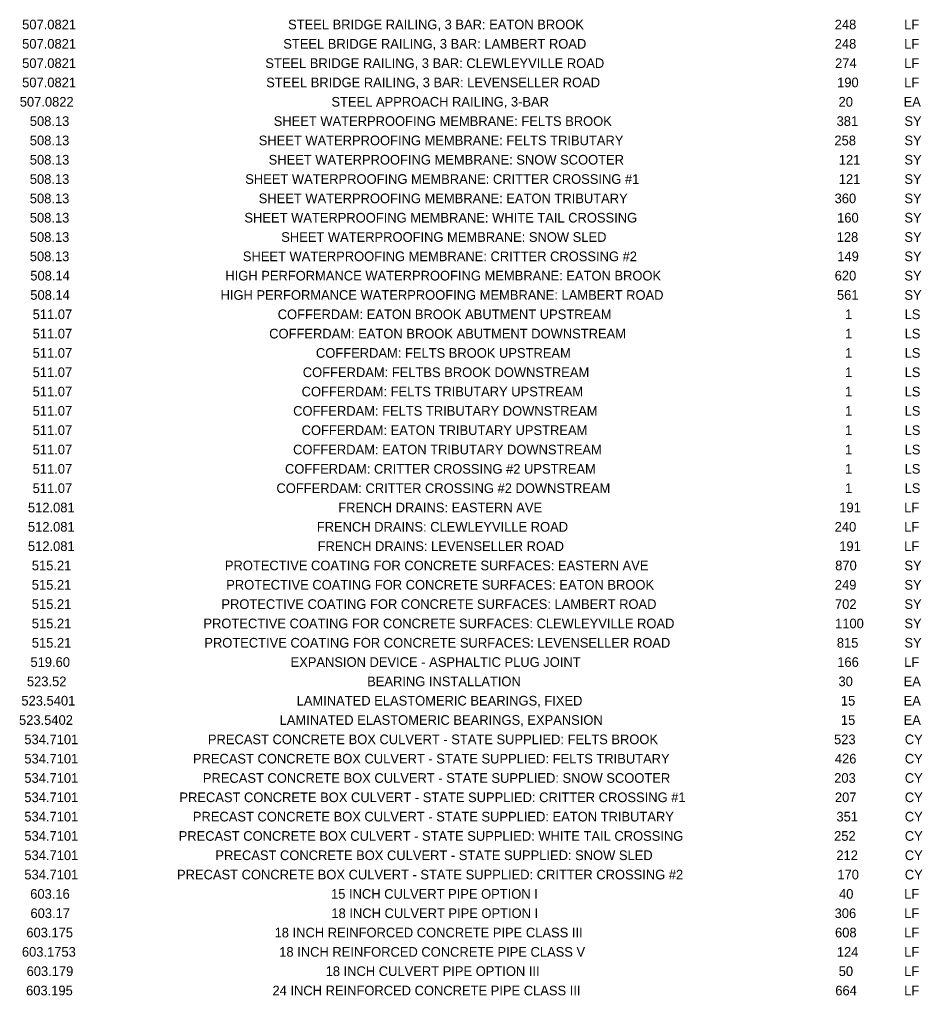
# Model space of a CAD drawing. Extents: x -18.7 to 5.6, y -2.7 to 5.1.
# Drawn here: x -18.677 to -17.757, y 1.164 to 2.159 of the extents above; entities that cross this region are included whole.
import ezdxf

# ---------------------------------------------------------------- set-up
doc = ezdxf.new("R2010")
doc.units = 0
doc.layers.add('ANNOTATION', color=7, linetype='Continuous')

msp = doc.modelspace()

# ---------------------------------------------------------------- texts
at = {"layer": 'ANNOTATION'}
for s, height, p in [('507.0821', 0.009843, (-18.674, 2.14859)), ('STEEL BRIDGE RAILING, 3 BAR: EATON BROOK', 0.009843, (-18.40311, 2.14859)), ('248', 0.009843, (-17.84626, 2.14859)), ('LF', 0.009843, (-17.77549, 2.14859)), ('507.0821', 0.009843, (-18.674, 2.1289)), ('STEEL BRIDGE RAILING, 3 BAR: LAMBERT ROAD', 0.009843, (-18.408, 2.1289)), ('248', 0.009843, (-17.84626, 2.1289)), ('LF', 0.009843, (-17.77549, 2.1289)), ('507.0821', 0.009843, (-18.674, 2.10921)), ('STEEL BRIDGE RAILING, 3 BAR: CLEWLEYVILLE ROAD', 0.009843, (-18.42633, 2.10921)), ('274', 0.009843, (-17.84592, 2.10921)), ('LF', 0.009843, (-17.77549, 2.10921)), ('507.0821', 0.009843, (-18.674, 2.08953)), ('STEEL BRIDGE RAILING, 3 BAR: LEVENSELLER ROAD', 0.009843, (-18.42543, 2.08953)), ('190', 0.009843, (-17.84382, 2.08953)), ('LF', 0.009843, (-17.77549, 2.08953)), ('507.0822', 0.009843, (-18.67644, 2.06984)), ('STEEL APPROACH RAILING, 3-BAR', 0.009843, (-18.35896, 2.06984)), ('20', 0.009843, (-17.84235, 2.06984)), ('EA', 0.009843, (-17.77611, 2.06984)), ('508.13', 0.009843, (-18.66621, 2.05016)), ('SHEET WATERPROOFING MEMBRANE: FELTS BROOK', 0.009843, (-18.41775, 2.05016)), ('381', 0.009843, (-17.84436, 2.05016)), ('SY', 0.009843, (-17.77526, 2.05016)), ('508.13', 0.009843, (-18.66621, 2.03047)), ('SHEET WATERPROOFING MEMBRANE: FELTS TRIBUTARY', 0.009843, (-18.43302, 2.03047)), ('258', 0.009843, (-17.84657, 2.03047)), ('SY', 0.009843, (-17.77526, 2.03047)), ('508.13', 0.009843, (-18.66621, 2.01078)), ('SHEET WATERPROOFING MEMBRANE: SNOW SCOOTER', 0.009843, (-18.4229, 2.01078)), ('121', 0.009843, (-17.84212, 2.01078)), ('SY', 0.009843, (-17.77526, 2.01078)), ('508.13', 0.009843, (-18.66621, 1.9911)), ('SHEET WATERPROOFING MEMBRANE: CRITTER CROSSING #1', 0.009843, (-18.44676, 1.9911)), ('121', 0.009843, (-17.84212, 1.9911)), ('SY', 0.009843, (-17.77526, 1.9911)), ('508.13', 0.009843, (-18.66621, 1.97141)), ('SHEET WATERPROOFING MEMBRANE: EATON TRIBUTARY', 0.009843, (-18.43306, 1.97141)), ('360', 0.009843, (-17.84638, 1.97141)), ('SY', 0.009843, (-17.77526, 1.97141)), ('508.13', 0.009843, (-18.66621, 1.95173)), ('SHEET WATERPROOFING MEMBRANE: WHITE TAIL CROSSING', 0.009843, (-18.44756, 1.95173)), ('160', 0.009843, (-17.84382, 1.95173)), ('SY', 0.009843, (-17.77526, 1.95173)), ('508.13', 0.009843, (-18.66621, 1.93204)), ('SHEET WATERPROOFING MEMBRANE: SNOW SLED', 0.009843, (-18.41009, 1.93204)), ('128', 0.009843, (-17.84425, 1.93204)), ('SY', 0.009843, (-17.77526, 1.93204)), ('508.13', 0.009843, (-18.66621, 1.91235)), ('SHEET WATERPROOFING MEMBRANE: CRITTER CROSSING #2', 0.009843, (-18.4492, 1.91235)), ('149', 0.009843, (-17.84367, 1.91235)), ('SY', 0.009843, (-17.77526, 1.91235)), ('508.14', 0.009843, (-18.6657, 1.89267)), ('HIGH PERFORMANCE WATERPROOFING MEMBRANE: EATON BROOK', 0.009843, (-18.467, 1.89267)), ('620', 0.009843, (-17.8463, 1.89267)), ('SY', 0.009843, (-17.77526, 1.89267)), ('508.14', 0.009843, (-18.6657, 1.87298)), ('HIGH PERFORMANCE WATERPROOFING MEMBRANE: LAMBERT ROAD', 0.009843, (-18.47189, 1.87298)), ('561', 0.009843, (-17.84398, 1.87298)), ('SY', 0.009843, (-17.77526, 1.87298)), ('511.07', 0.009843, (-18.6633, 1.8533)), ('COFFERDAM: EATON BROOK ABUTMENT UPSTREAM', 0.009843, (-18.41366, 1.8533)), ('1', 0.00984, (-17.83576, 1.8533)), ('LS', 0.009843, (-17.77506, 1.8533)), ('511.07', 0.009843, (-18.6633, 1.83361)), ('COFFERDAM: EATON BROOK ABUTMENT DOWNSTREAM', 0.009843, (-18.42234, 1.83361)), ('1', 0.00984, (-17.83576, 1.83361)), ('LS', 0.009843, (-17.77506, 1.83361)), ('511.07', 0.009843, (-18.6633, 1.81392)), ('COFFERDAM: FELTS BROOK UPSTREAM', 0.009843, (-18.37471, 1.81392)), ('1', 0.00984, (-17.83576, 1.81392)), ('LS', 0.009843, (-17.77506, 1.81392)), ('511.07', 0.009843, (-18.6633, 1.79424)), ('COFFERDAM: FELTBS BROOK DOWNSTREAM', 0.009843, (-18.38812, 1.79424)), ('1', 0.00984, (-17.83576, 1.79424)), ('LS', 0.009843, (-17.77506, 1.79424)), ('511.07', 0.009843, (-18.6633, 1.77455)), ('COFFERDAM: FELTS TRIBUTARY UPSTREAM', 0.009843, (-18.38928, 1.77455)), ('1', 0.00984, (-17.83576, 1.77455)), ('LS', 0.009843, (-17.77506, 1.77455)), ('511.07', 0.009843, (-18.6633, 1.75487)), ('COFFERDAM: FELTS TRIBUTARY DOWNSTREAM', 0.009843, (-18.39796, 1.75487)), ('1', 0.00984, (-17.83576, 1.75487)), ('LS', 0.009843, (-17.77506, 1.75487)), ('511.07', 0.009843, (-18.6633, 1.73518)), ('COFFERDAM: EATON TRIBUTARY UPSTREAM', 0.009843, (-18.38932, 1.73518)), ('1', 0.00984, (-17.83576, 1.73518)), ('LS', 0.009843, (-17.77506, 1.73518)), ('511.07', 0.009843, (-18.6633, 1.71549)), ('COFFERDAM: EATON TRIBUTARY DOWNSTREAM', 0.009843, (-18.398, 1.71549)), ('1', 0.00984, (-17.83576, 1.71549)), ('LS', 0.009843, (-17.77506, 1.71549)), ('511.07', 0.009843, (-18.6633, 1.69581)), ('COFFERDAM: CRITTER CROSSING #2 UPSTREAM', 0.009843, (-18.40627, 1.69581)), ('1', 0.00984, (-17.83576, 1.69581)), ('LS', 0.009843, (-17.77506, 1.69581)), ('511.07', 0.009843, (-18.6633, 1.67612)), ('COFFERDAM: CRITTER CROSSING #2 DOWNSTREAM', 0.009843, (-18.41496, 1.67612)), ('1', 0.00984, (-17.83576, 1.67612)), ('LS', 0.009843, (-17.77506, 1.67612)), ('512.081', 0.009843, (-18.6681, 1.65644)), ('FRENCH DRAINS: EASTERN AVE', 0.009843, (-18.35201, 1.65644)), ('191', 0.009843, (-17.84165, 1.65644)), ('LF', 0.009843, (-17.77549, 1.65644)), ('512.081', 0.009843, (-18.6681, 1.63675)), ('FRENCH DRAINS: CLEWLEYVILLE ROAD', 0.009843, (-18.37387, 1.63675)), ('240', 0.009843, (-17.8463, 1.63675)), ('LF', 0.009843, (-17.77549, 1.63675)), ('512.081', 0.009843, (-18.6681, 1.61706)), ('FRENCH DRAINS: LEVENSELLER ROAD', 0.009843, (-18.37297, 1.61706)), ('191', 0.009843, (-17.84165, 1.61706)), ('LF', 0.009843, (-17.77549, 1.61706)), ('515.21', 0.009843, (-18.66415, 1.59738)), ('PROTECTIVE COATING FOR CONCRETE SURFACES: EASTERN AVE', 0.009843, (-18.46749, 1.59738)), ('870', 0.009843, (-17.84576, 1.59738)), ('SY', 0.009843, (-17.77526, 1.59738)), ('515.21', 0.009843, (-18.66415, 1.57769)), ('PROTECTIVE COATING FOR CONCRETE SURFACES: EATON BROOK', 0.009843, (-18.46613, 1.57769)), ('249', 0.009843, (-17.84615, 1.57769)), ('SY', 0.009843, (-17.77526, 1.57769)), ('515.21', 0.009843, (-18.66415, 1.55801)), ('PROTECTIVE COATING FOR CONCRETE SURFACES: LAMBERT ROAD', 0.009843, (-18.47102, 1.55801)), ('702', 0.009843, (-17.84603, 1.55801)), ('SY', 0.009843, (-17.77526, 1.55801)), ('515.21', 0.009843, (-18.66415, 1.53832)), ('PROTECTIVE COATING FOR CONCRETE SURFACES: CLEWLEYVILLE ROAD', 0.009843, (-18.48935, 1.53832)), ('1100', 0.009843, (-17.84591, 1.53832)), ('SY', 0.009843, (-17.77526, 1.53832)), ('515.21', 0.009843, (-18.66415, 1.51863)), ('PROTECTIVE COATING FOR CONCRETE SURFACES: LEVENSELLER ROAD', 0.009843, (-18.48845, 1.51863)), ('815', 0.009843, (-17.84409, 1.51863)), ('SY', 0.009843, (-17.77526, 1.51863)), ('519.60', 0.009843, (-18.66555, 1.49895)), ('EXPANSION DEVICE - ASPHALTIC PLUG JOINT', 0.009843, (-18.4006, 1.49895)), ('166', 0.009843, (-17.84367, 1.49895)), ('LF', 0.009843, (-17.77549, 1.49895)), ('523.52', 0.009843, (-18.66915, 1.47926)), ('BEARING INSTALLATION', 0.009843, (-18.32257, 1.47926)), ('30', 0.009843, (-17.84243, 1.47926)), ('EA', 0.009843, (-17.77611, 1.47926)), ('523.5401', 0.009843, (-18.67477, 1.45958)), ('LAMINATED ELASTOMERIC BEARINGS, FIXED', 0.009843, (-18.39438, 1.45958)), ('15', 0.009843, (-17.83999, 1.45958)), ('EA', 0.009843, (-17.77611, 1.45958)), ('523.5402', 0.009843, (-18.67721, 1.43989)), ('LAMINATED ELASTOMERIC BEARINGS, EXPANSION', 0.009843, (-18.4117, 1.43989)), ('15', 0.009843, (-17.83999, 1.43989)), ('EA', 0.009843, (-17.77611, 1.43989)), ('534.7101', 0.009843, (-18.67175, 1.4202)), ('PRECAST CONCRETE BOX CULVERT - STATE SUPPLIED: FELTS BROOK', 0.009843, (-18.4848, 1.4202)), ('523', 0.009843, (-17.84696, 1.4202)), ('CY', 0.009843, (-17.77487, 1.4202)), ('534.7101', 0.009843, (-18.67175, 1.40052)), ('PRECAST CONCRETE BOX CULVERT - STATE SUPPLIED: FELTS TRIBUTARY', 0.009843, (-18.50006, 1.40052)), ('426', 0.009843, (-17.84615, 1.40052)), ('CY', 0.009843, (-17.77487, 1.40052)), ('534.7101', 0.009843, (-18.67175, 1.38083)), ('PRECAST CONCRETE BOX CULVERT - STATE SUPPLIED: SNOW SCOOTER', 0.009843, (-18.48995, 1.38083)), ('203', 0.009843, (-17.84681, 1.38083)), ('CY', 0.009843, (-17.77487, 1.38083)), ('534.7101', 0.009843, (-18.67175, 1.36115)), ('PRECAST CONCRETE BOX CULVERT - STATE SUPPLIED: CRITTER CROSSING #1', 0.009843, (-18.51381, 1.36115)), ('207', 0.009843, (-17.84607, 1.36115)), ('CY', 0.009843, (-17.77487, 1.36115)), ('534.7101', 0.009843, (-18.67175, 1.34146)), ('PRECAST CONCRETE BOX CULVERT - STATE SUPPLIED: EATON TRIBUTARY', 0.009843, (-18.50011, 1.34146)), ('351', 0.009843, (-17.84452, 1.34146)), ('CY', 0.009843, (-17.77487, 1.34146)), ('534.7101', 0.009843, (-18.67175, 1.32177)), ('PRECAST CONCRETE BOX CULVERT - STATE SUPPLIED: WHITE TAIL CROSSING', 0.009843, (-18.5146, 1.32177)), ('252', 0.009843, (-17.84688, 1.32177)), ('CY', 0.009843, (-17.77487, 1.32177)), ('534.7101', 0.009843, (-18.67175, 1.30209)), ('PRECAST CONCRETE BOX CULVERT - STATE SUPPLIED: SNOW SLED', 0.009843, (-18.47714, 1.30209)), ('212', 0.009843, (-17.84456, 1.30209)), ('CY', 0.009843, (-17.77487, 1.30209)), ('534.7101', 0.009843, (-18.67175, 1.2824)), ('PRECAST CONCRETE BOX CULVERT - STATE SUPPLIED: CRITTER CROSSING #2', 0.009843, (-18.51625, 1.2824)), ('170', 0.009843, (-17.84359, 1.2824)), ('CY', 0.009843, (-17.77487, 1.2824)), ('603.16', 0.009843, (-18.66578, 1.26272)), ('15 INCH CULVERT PIPE OPTION I', 0.009843, (-18.35932, 1.26272)), ('40', 0.009843, (-17.84189, 1.26272)), ('LF', 0.009843, (-17.77549, 1.26272)), ('603.17', 0.009843, (-18.66555, 1.24303)), ('18 INCH CULVERT PIPE OPTION I', 0.009843, (-18.35901, 1.24303)), ('306', 0.009843, (-17.84638, 1.24303)), ('LF', 0.009843, (-17.77549, 1.24303)), ('603.175', 0.009843, (-18.66977, 1.22334)), ('18 INCH REINFORCED CONCRETE PIPE CLASS III', 0.009843, (-18.41684, 1.22334)), ('608', 0.009843, (-17.84595, 1.22334)), ('LF', 0.009843, (-17.77549, 1.22334)), ('603.1753', 0.009843, (-18.67426, 1.20366)), ('18 INCH REINFORCED CONCRETE PIPE CLASS V', 0.009843, (-18.41211, 1.20366)), ('124', 0.009843, (-17.84413, 1.20366)), ('LF', 0.009843, (-17.77549, 1.20366)), ('603.179', 0.009843, (-18.6695, 1.18397)), ('18 INCH CULVERT PIPE OPTION III', 0.009843, (-18.36485, 1.18397)), ('50', 0.009843, (-17.8422, 1.18397)), ('LF', 0.009843, (-17.77549, 1.18397)), ('603.195', 0.009843, (-18.67, 1.16429)), ('24 INCH REINFORCED CONCRETE PIPE CLASS III', 0.009843, (-18.41901, 1.16429)), ('664', 0.009843, (-17.84568, 1.16429)), ('LF', 0.009843, (-17.77549, 1.16429))]:
    msp.add_text(s, height=height, dxfattribs=at).set_placement(p)

doc.saveas('drawing.dxf')
